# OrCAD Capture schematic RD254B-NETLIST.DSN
size Custom
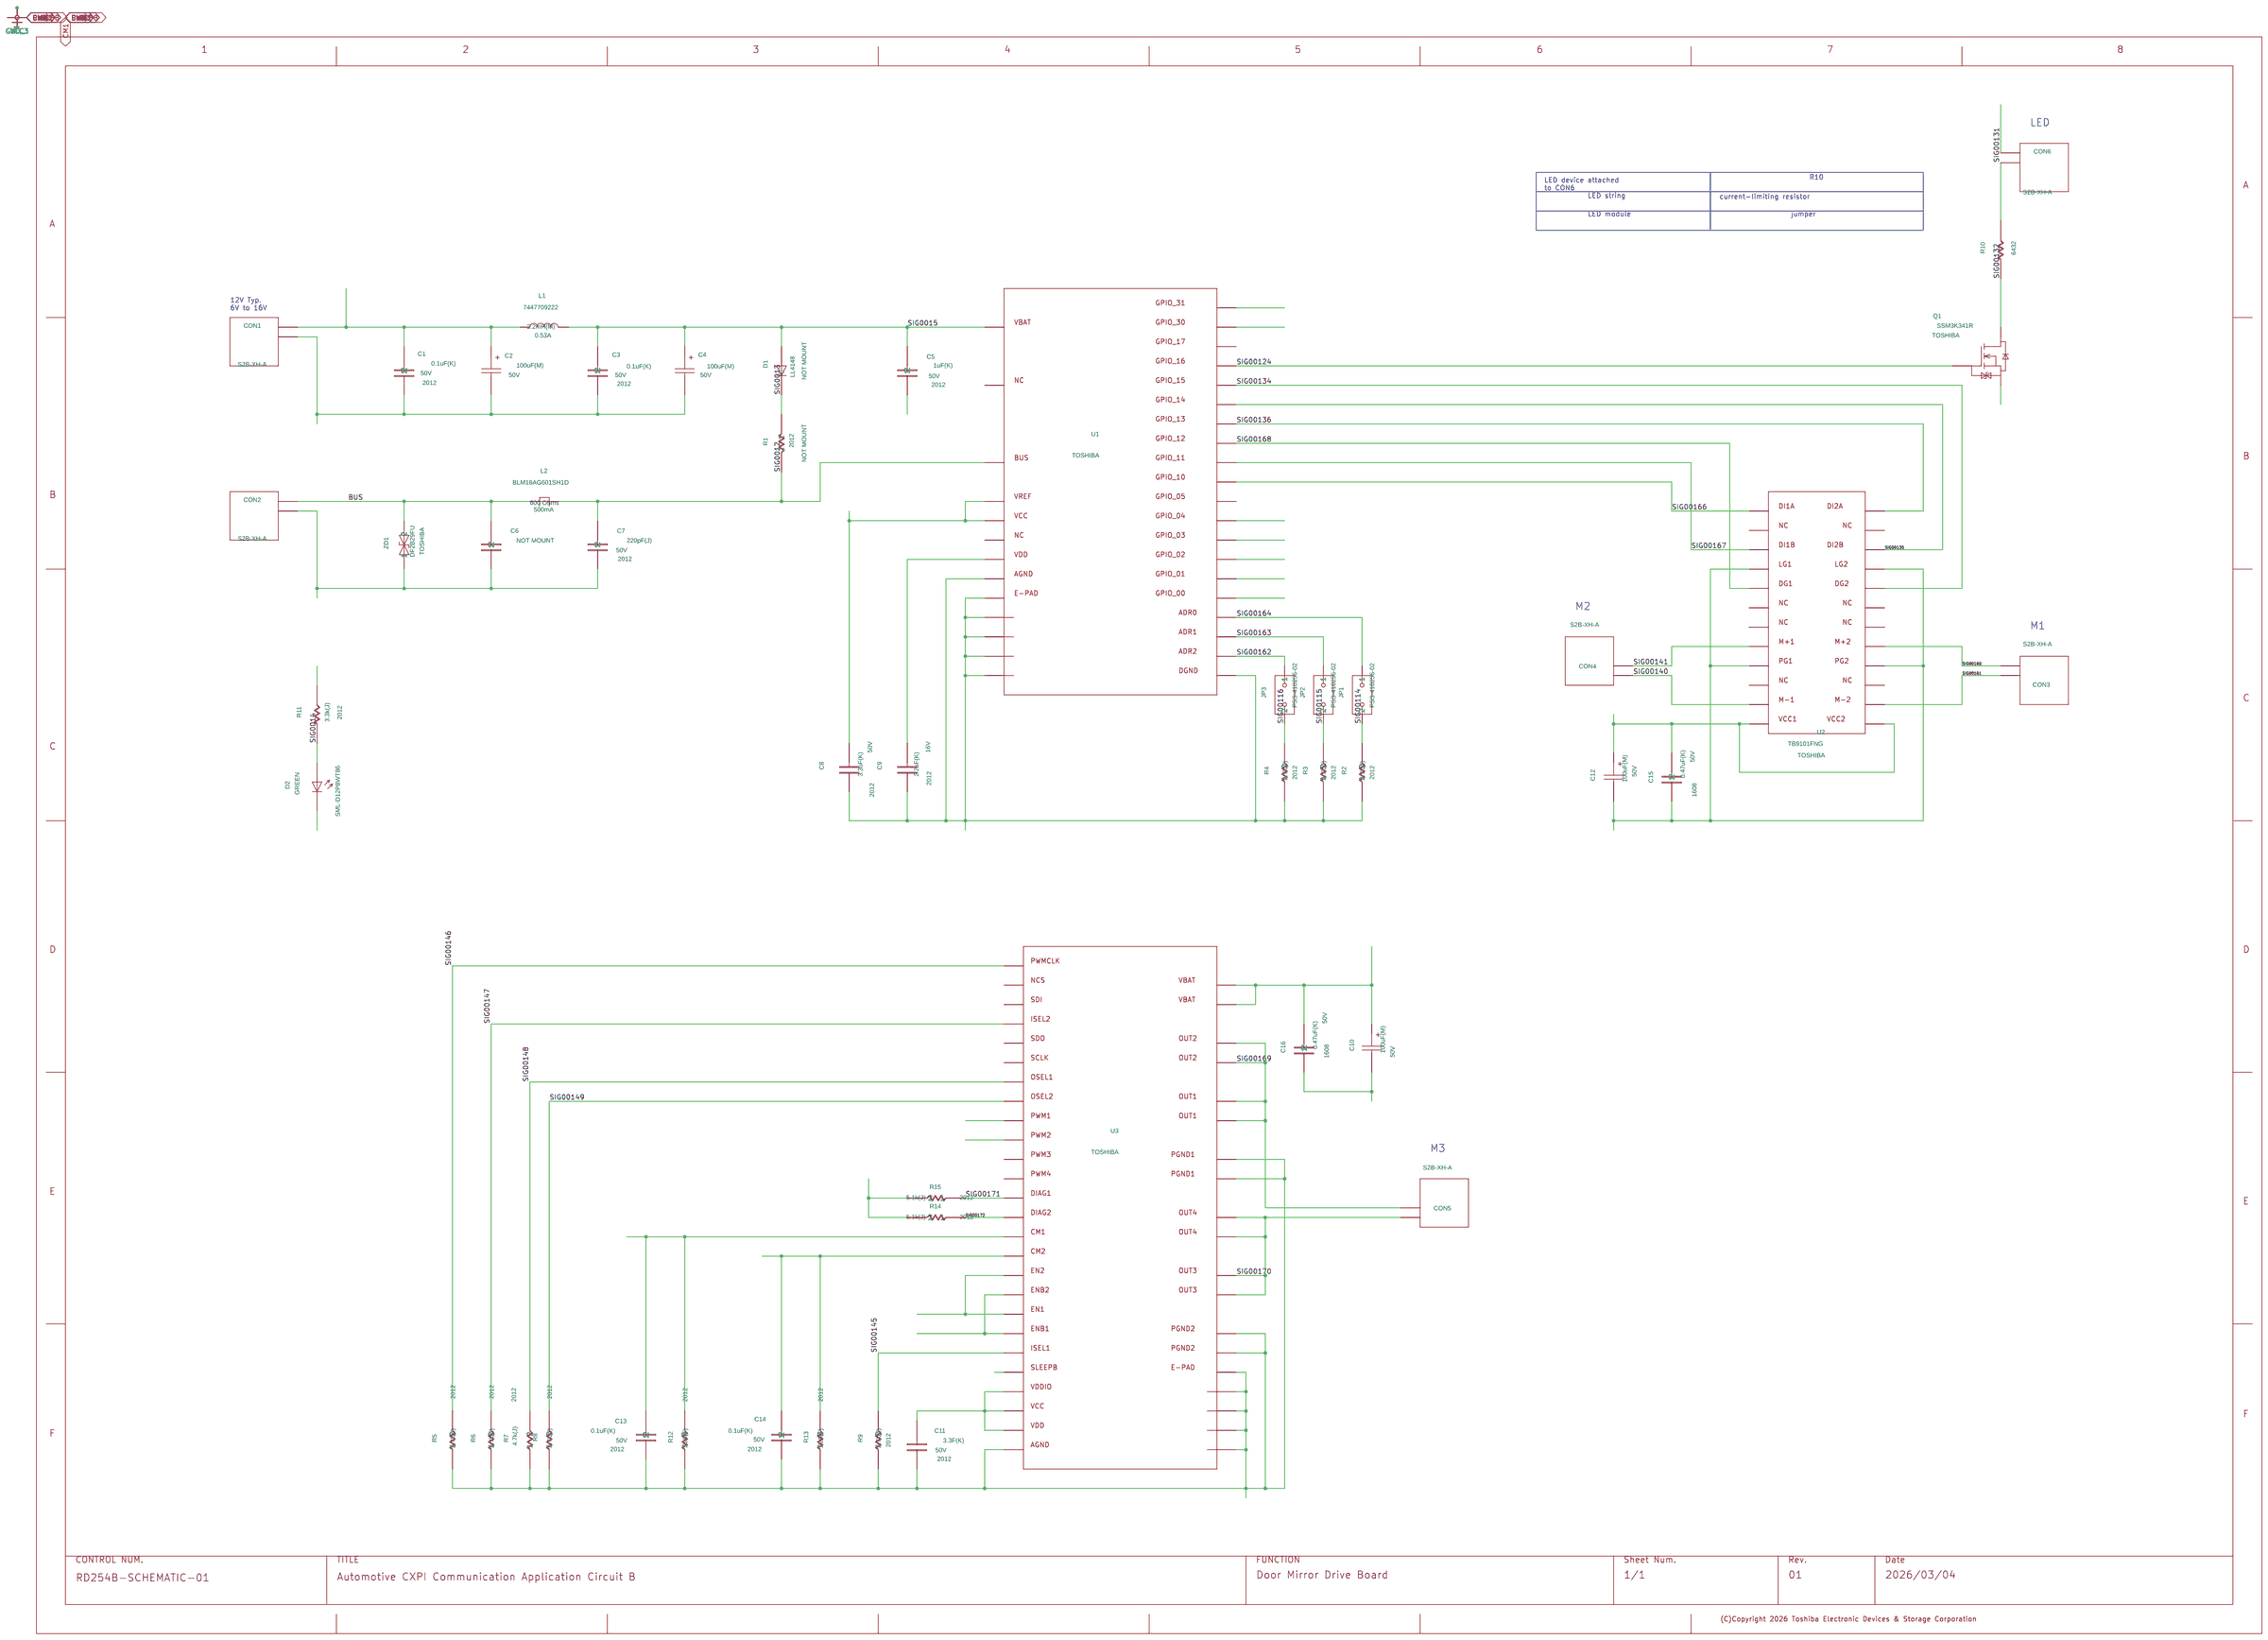
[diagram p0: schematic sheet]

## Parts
C1  C
C2  CP
C3  C
C4  CP
C5  C
C6  C
C7  C
C8  C
C9  C
C10  CP
C11  C
C12  CP
C13  C
C14  C
C15  C
C16  C
CON1  S2B-XH-A
CON2  S2B-XH-A
CON3  S2B-XH-A
CON4  S2B-XH-A
CON5  S2B-XH-A
CON6  S2B-XH-A
D1  D
D2  LED
JP1  PSS-410256-02
JP2  PSS-410256-02
JP3  PSS-410256-02
L1  L
L2  FB
Q1  SSM3K341R
R1  R
R2  R
R3  R
R4  R
R5  R
R6  R
R7  R
R8  R
R9  R
R10  R
R11  R
R12  R
R13  R
R14  R
R15  R
U1  TB9033FTGIC_VERB
U2  TB9101FNG
U3  TB9054FTG_VERB
U?#1  WAKU_DEF_A3_1
ZD1  ZDB

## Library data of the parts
C1 C3 C13 C14 = C: COMPONENTTYPE: 4; SAVECOUNT: 0; SIZECODESMD: 2012; VAL1: 0.1uF(K); VAL2: 50V
C2 C4 C10 C12 = CP: COMP: C; COMPONENTTYPE: 4; VAL1: 100uF(M); VAL2: 50V
C5 = C: COMPONENTTYPE: 4; SAVECOUNT: 0; SIZECODESMD: 2012; VAL1: 1uF(K); VAL2: 50V
C6 = C: COMPONENTTYPE: 4; NOTMOUNT: NOT MOUNT; SAVECOUNT: 0
C7 = C: COMPONENTTYPE: 4; SAVECOUNT: 0; SIZECODESMD: 2012; VAL1: 220pF(J); VAL2: 50V
C8 = C#1: COMPONENTTYPE: 4; CaptureCellPackProp: C##1; SAVECOUNT: 0; SIZECODESMD: 2012; VAL1: 3.3uF(K); VAL2: 50V
C9 = C#1: COMPONENTTYPE: 4; CaptureCellPackProp: C##1; SAVECOUNT: 0; SIZECODESMD: 2012; VAL1: 2.2uF(K); VAL2: 16V
C11 = C#1: COMPONENTTYPE: 4; CaptureCellPackProp: C##1; SAVECOUNT: 0; SIZECODESMD: 2012; VAL1: 3.3F(K); VAL2: 50V
C15 C16 = C: COMPONENTTYPE: 4; SAVECOUNT: 0; SIZECODESMD: 1608; VAL1: 0.47uF(K); VAL2: 50V
CON1-CON6 = S2B-XH-A: COMPONENTTYPE: 4
D1 = D: COMP: LL4148; COMPONENTTYPE: 4; NOTMOUNT: NOT MOUNT; VAL3: LL4148
D2 = LED: COMPONENTTYPE: 4; VAL2: GREEN; VAL3: SML-D12P8WT86
JP1-JP3 = PSS-410256-02: COMPONENTKIND: 135; COMPONENTTYPE: 4
L1 = L: COMP: 7447709222; COMPONENTTYPE: 4; SAVECOUNT: 0; VAL1: 2.2mH(M); VAL2: 0.53A; VAL3: 7447709222
L2 = FB: COMP: BLM18AG601SH1D; COMPONENTTYPE: 4; VAL1: 600 Ohms; VAL2: 500mA; VAL3: BLM18AG601SH1D
Q1 = SSM3K341R: COMPONENTTYPE: 4; USERCOMPTEXT3: TOSHIBA
R1 = R: COMPONENTTYPE: 4; NOTMOUNT: NOT MOUNT; SAVECOUNT: 0; SIZECODESMD: 2012; VAL1: 1k(J); VAL2: 250mW
R2-R9 = R: COMPONENTTYPE: 4; SAVECOUNT: 0; SIZECODESMD: 2012; VAL1: 4.7k(J); VAL2: 250mW
R10 = R#2: COMPONENTTYPE: 4; CaptureCellPackProp: R##2; SAVECOUNT: 0; SIZECODESMD: 6432; VAL1: 0; VAL2: 2W
R11 = R#1: COMPONENTTYPE: 4; CaptureCellPackProp: R##1; SAVECOUNT: 0; SIZECODESMD: 2012; VAL1: 3.3k(J); VAL2: 250mW
R12 R13 = R: COMPONENTTYPE: 4; SAVECOUNT: 0; SIZECODESMD: 2012; VAL1: 220(F); VAL2: 250mW
R14 R15 = R: COMPONENTTYPE: 4; SAVECOUNT: 0; SIZECODESMD: 2012; VAL1: 5.1k(J); VAL2: 250mW
U1 = TB9033FTGIC_VERB: COMPONENTTYPE: 4; USERCOMPTEXT3: TOSHIBA
U2 = TB9101FNG: COMPONENTTYPE: 4; USERCOMPTEXT3: TOSHIBA
U3 = TB9054FTG_VERB: COMPONENTTYPE: 4; USERCOMPTEXT3: TOSHIBA
U?#1 = WAKU_DEF_A3_1: AUTHOR: t5459927; COMPONENTTYPE: 2; DATE: 2026/03/04; DRAWINGNUMBER: RD254B-SCHEMATIC-01; FUNCTION: Door Mirror Drive Board; REVISION: 01; SAVECOUNT: 4; SHEETNUMBER: 1/1; SHTSAVECOUNT: 71; TIME: 16:57:06; TITLE: Automotive CXPI Communication Application Circuit B; UPDATEDATE: 2026.4.22; UPDATETIME: 10:24:54
ZD1 = ZDB: COMP: DF2B29FU; COMPONENTTYPE: 4; USERCOMPTEXT3: TOSHIBA; VAL3: DF2B29FU

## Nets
GND: C1.2(1) C2.1 C3.2(1) C4.1 C5.2(1) C6.2(1) C7.2(1) C8.1 C9.1 C10.1 C11.1 C12.1 C13.2(1) C14.2(1) C15.2(1) C16.2(1) CON1.1 CON2.1 D2.C Q1.2 R2.2(1) R3.2(1) R4.2(1) R5.2(1) R6.2(1) R7.2(1) R8.2(1) R9.2(1) R12.2(1) R13.2(1) U1.1T U1.2T U1.3T U1.4T U1.26 U1.27 U1.E_PAD U2.4 U2.9 U2.16 U2.21 U3.1T U3.2T U3.3T U3.4T U3.7 U3.19 U3.20 U3.31 U3.32 U3.E_PAD ZD1.2(1)
VBAT: C1.1(2) C2.2 C10.2 C12.2 C15.1(2) C16.1(2) CON1.2 CON6.2 L1.1 R11.2 U2.12 U2.13 U3.25 U3.26
BUS: C6.1(2) CON2.2 L2.1 ZD1.1(2)
CM1: C13.1(2) R12.1(2) U1.9 U3.15
CM2: C14.1(2) R13.1(2) U1.10 U3.16
EN: U1.7 U3.33 U3.35
ENB: U1.6 U3.34 U3.36
PWM1: U1.21 U3.11
PWM2: U1.20 U3.12
SIG0012: C7.1(2) L2.2 R1.1(2) U1.28
SIG0013: D1.K(C) R1.2(1)
SIG0014: D2.A R11.1
SIG0015: C3.1(2) C4.2 C5.1(2) D1.A L1.2 U1.1
SIG00114: JP1.1(2) R2.1(2)
SIG00115: JP2.1(2) R3.1(2)
SIG00116: JP3.1(2) R4.1(2)
SIG00124: Q1.1 U1.18
SIG00131: CON6.1 R10.P_2
SIG00132: Q1.3 R10.P_1
SIG00134: U1.17 U2.20
SIG00135: U1.16 U2.22
SIG00136: U1.15 U2.24
SIG00140: CON4.2 U2.11
SIG00141: CON4.1 U2.8
SIG00145: R9.1(2) U3.39
SIG00146: R5.1(2) U3.1
SIG00147: R6.1(2) U3.5
SIG00148: R7.1(2) U3.9
SIG00149: R8.1(2) U3.10
SIG00160: CON3.2 U2.17
SIG00161: CON3.1 U2.14
SIG00162: JP3.2(1) U1.5
SIG00163: JP2.2(1) U1.4
SIG00164: JP1.2(1) U1.3
SIG00166: U1.12 U2.1
SIG00167: U1.13 U2.3
SIG00168: U1.14 U2.5
SIG00169: CON5.1 U3.21 U3.22 U3.23 U3.24
SIG00170: CON5.2 U3.27 U3.28 U3.29 U3.30
SIG00171: R15.2(1) U3.17
SIG00172: R14.2(1) U3.18
SLEEPB: U1.8 U3.40
VP_1R5_B: C9.2 U1.22
VP_5R0_B: C8.2 C11.2 R14.1(2) R15.1(2) U1.24 U1.25 U3.2 U3.37 U3.38

Not connected (* = marked no-connect by the designer): U1 2 11 19 23; U2 2 6 7 10 15 18 19 23; U3 3 4 6 8 13 14

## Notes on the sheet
- LED
- R10
- LED device attached
  to CON6
- LED string
- current-limiting resistor
- LED module
- jumper
- 12V Typ.
  6V to 16V
- M2
- M1
- M3
